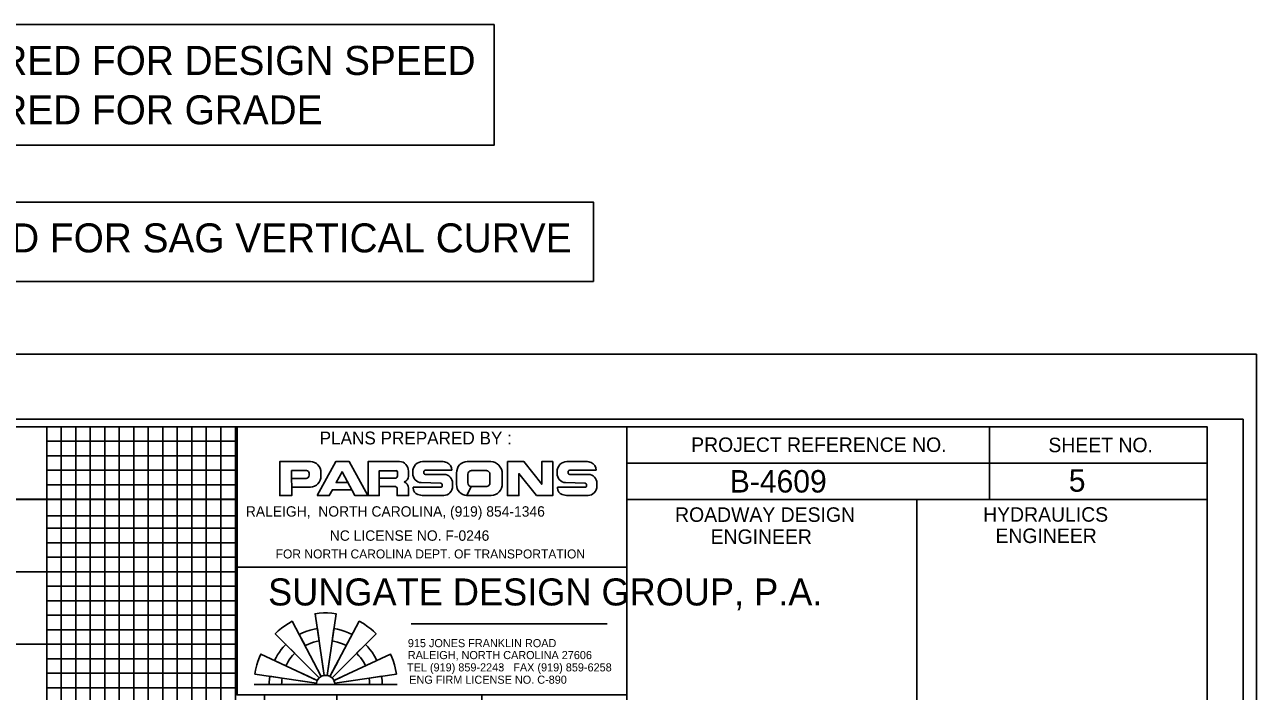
# Model space of a CAD drawing. Extents: x 1735444 to 1737729, y 696688 to 698970.
# Drawn here: x 1737304.4 to 1737729.1, y 698618.9 to 698848.7 of the extents above; entities that cross this region are included whole.
import ezdxf

# ---------------------------------------------------------------- set-up
doc = ezdxf.new("R2010")
doc.units = 0
for name, color, linetype in [('Default', 7, 'Continuous'), ('Old_Level_2', 7, 'Continuous'), ('Prop Grid Mask', 7, 'Continuous'), ('Prop VPI Label', 7, 'Continuous'), ('Sheet Cutting Line CELL', 7, 'Continuous'), ('Sheet Data Field CELL', 7, 'Continuous'), ('Sheet DOT Grid CELL', 7, 'Continuous'), ('Sheet Layout Profile Border', 7, 'Continuous'), ('Sheet Plot Border Inside CELL', 7, 'Continuous'), ('Sheet Plot Border Outside CELL', 7, 'Continuous'), ('Sheet Profile CELL', 7, 'Continuous'), ('Sheet Profile Grid Major CELL', 7, 'Continuous'), ('Sheet Profile Grid Middle CELL', 7, 'Continuous'), ('Sheet Profile Grid Minor CELL', 7, 'Continuous')]:
    doc.layers.add(name, color=color, linetype=linetype)

msp = doc.modelspace()

# ---------------------------------------------------------------- linework, layer by layer
at = {"layer": 'Default'}
for p, q in [((1737437.74, 698642.18), (1737505.24, 698642.18)), ((1737401.13, 698634.69), (1737401.13, 698634.69)), ((1737415.34, 698634.69), (1737415.34, 698634.69)), ((1737401.99, 698627.54), (1737405.96, 698623.53)), ((1737406.71, 698624.08), (1737404.06, 698629.07)), ((1737407.74, 698624.42), (1737406.91, 698630)), ((1737408.68, 698624.42), (1737409.5, 698630)), ((1737409.7, 698624.08), (1737412.36, 698629.07)), ((1737414.43, 698627.54), (1737410.45, 698623.53)), ((1737390.95, 698623.81), (1737390.95, 698623.81)), ((1737405.32, 698622.62), (1737400.21, 698625.02)), ((1737401.61, 698624.38), (1737401.61, 698624.38)), ((1737411.09, 698622.62), (1737416.2, 698625.02)), ((1737414.04, 698624.01), (1737411.09, 698622.62)), ((1737383.53, 698621.27), (1737432.88, 698621.27)), ((1737405.05, 698621.73), (1737399.47, 698622.57)), ((1737411.36, 698621.73), (1737416.95, 698622.57))]:
    msp.add_line(p, q, dxfattribs=at)
for points in [[(1737377.67, 698661.7), (1737512.07, 698661.7), (1737512.07, 698617.69), (1737377.67, 698617.69)], [(1737407.74, 698624.42), (1737404.59, 698645.68), (1737405.96, 698645.84), (1737407.49, 698645.93), (1737408.79, 698645.94), (1737410.36, 698645.85), (1737411.82, 698645.68), (1737408.68, 698624.42)], [(1737405.96, 698623.53), (1737390.83, 698638.79), (1737391.85, 698639.74), (1737392.99, 698640.69), (1737394.13, 698641.53), (1737395.38, 698642.35), (1737396.62, 698643.05), (1737406.71, 698624.08)], [(1737399.06, 698638.48), (1737399.98, 698638.94), (1737401.4, 698639.53), (1737402.92, 698640.03), (1737404.29, 698640.36), (1737405.35, 698640.55), (1737405.99, 698636.27), (1737404.98, 698636.09), (1737404.03, 698635.85), (1737403.05, 698635.53), (1737402.01, 698635.11), (1737401.09, 698634.66)], [(1737409.7, 698624.08), (1737419.79, 698643.05), (1737421.21, 698642.24), (1737422.78, 698641.18), (1737423.76, 698640.42), (1737424.69, 698639.63), (1737425.58, 698638.78), (1737410.45, 698623.53)], [(1737411.06, 698640.55), (1737412.24, 698640.34), (1737413.56, 698640.01), (1737414.89, 698639.58), (1737416.09, 698639.09), (1737417.36, 698638.48), (1737415.33, 698634.66), (1737414.61, 698635.02), (1737413.66, 698635.42), (1737412.29, 698635.88), (1737411.34, 698636.11), (1737410.43, 698636.27)], [(1737405.05, 698621.73), (1737383.8, 698624.87), (1737384.02, 698626.16), (1737384.48, 698628.04), (1737384.84, 698629.19), (1737385.39, 698630.65), (1737385.87, 698631.75), (1737405.32, 698622.62)], [(1737390.56, 698629.54), (1737391.11, 698630.63), (1737391.61, 698631.49), (1737392.26, 698632.47), (1737392.9, 698633.33), (1737393.61, 698634.18), (1737394.48, 698635.11), (1737397.53, 698632.04), (1737396.79, 698631.26), (1737396.22, 698630.57), (1737395.68, 698629.82), (1737395.15, 698628.98), (1737394.77, 698628.3), (1737394.47, 698627.7)], [(1737411.08, 698622.6), (1737430.54, 698631.76), (1737431, 698630.73), (1737431.47, 698629.5), (1737431.92, 698628.09), (1737432.22, 698626.98), (1737432.62, 698624.88), (1737411.36, 698621.73)], [(1737421.93, 698635.11), (1737422.72, 698634.28), (1737423.49, 698633.37), (1737424.2, 698632.42), (1737425.07, 698631.04), (1737425.85, 698629.56), (1737421.94, 698627.72), (1737421.44, 698628.69), (1737420.77, 698629.77), (1737420.22, 698630.53), (1737419.69, 698631.18), (1737418.89, 698632.04)], [(1737388.72, 698621.27), (1737388.73, 698622.11), (1737388.8, 698623.1), (1737388.92, 698624.11), (1737393.2, 698623.48), (1737393.11, 698622.76), (1737393.06, 698622.02), (1737393.04, 698621.27)], [(1737405.02, 698621.27), (1737405.03, 698621.51), (1737405.05, 698621.72), (1737405.17, 698622.23), (1737405.32, 698622.62), (1737405.48, 698622.91), (1737405.65, 698623.17), (1737405.82, 698623.38), (1737405.96, 698623.53), (1737406.33, 698623.84), (1737406.71, 698624.08), (1737406.98, 698624.21), (1737407.28, 698624.31), (1737407.55, 698624.38), (1737407.74, 698624.42), (1737408.22, 698624.45), (1737408.68, 698624.42), (1737408.95, 698624.37), (1737409.18, 698624.3), (1737409.43, 698624.21), (1737409.7, 698624.08), (1737410.1, 698623.83), (1737410.45, 698623.53), (1737410.63, 698623.34), (1737410.8, 698623.11), (1737410.94, 698622.9), (1737411.09, 698622.62), (1737411.27, 698622.16), (1737411.36, 698621.73), (1737411.39, 698621.49), (1737411.39, 698621.27)], [(1737427.49, 698624.12), (1737427.65, 698622.64), (1737427.7, 698621.3), (1737423.38, 698621.27), (1737423.34, 698622.37), (1737423.21, 698623.49)]]:
    msp.add_lwpolyline(points, close=True, dxfattribs=at)
for start, end in [(359.9999, 179.9999), (179.9999, 359.9999)]:
    msp.add_arc((1737468.51, 698627.29), 0.138, start, end, dxfattribs=at)
at = {"layer": 'Old_Level_2'}
for p, q in [((1737377.67, 698710.13), (1737512.07, 698710.13)), ((1737377.67, 698661.7), (1737377.67, 698710.13)), ((1737512.07, 698661.7), (1737512.07, 698710.13)), ((1737448.26, 698698.11), (1737441.61, 698698.11)), ((1737465.13, 698698.11), (1737457, 698698.11)), ((1737498.01, 698698.11), (1737491.36, 698698.11)), ((1737402.49, 698693.37), (1737402.49, 698694.06)), ((1737406.57, 698694.29), (1737406.57, 698693.14)), ((1737432.98, 698693.14), (1737432.98, 698694.44)), ((1737436.77, 698694.83), (1737436.77, 698693.06)), ((1737438.25, 698694.52), (1737438.25, 698694.05)), ((1737442.68, 698695.13), (1737451.68, 698695.13)), ((1737449.11, 698693.68), (1737442.68, 698693.68)), ((1737453.32, 698694.14), (1737453.32, 698690.23)), ((1737457.28, 698690.77), (1737457.28, 698693.75)), ((1737458.41, 698694.98), (1737463.72, 698694.98)), ((1737464.85, 698693.75), (1737464.85, 698690.77)), ((1737469.1, 698690.54), (1737469.1, 698693.83)), ((1737488.01, 698694.52), (1737488.01, 698694.05)), ((1737492.44, 698695.13), (1737501.44, 698695.13)), ((1737498.87, 698693.68), (1737492.44, 698693.68)), ((1737441.19, 698690.84), (1737447.75, 698690.69)), ((1737451.97, 698689.69), (1737451.97, 698690.62)), ((1737456.86, 698686.41), (1737458.41, 698689.55)), ((1737490.95, 698690.84), (1737497.51, 698690.69)), ((1737501.73, 698689.69), (1737501.72, 698690.62)), ((1737442.04, 698686.41), (1737448.9, 698686.41)), ((1737456.86, 698686.41), (1737465.28, 698686.41)), ((1737491.79, 698686.41), (1737498.66, 698686.41)), ((1737512.07, 698661.7), (1737377.67, 698661.7))]:
    msp.add_line(p, q, dxfattribs=at)
for points in [[(1737401.63, 698694.98), (1737396.47, 698694.98), (1737396.47, 698692.3), (1737396.54, 698689.31), (1737396.54, 698686.41), (1737392.38, 698686.41), (1737392.38, 698698.11), (1737402.99, 698698.11)], [(1737432.48, 698694.97), (1737426.69, 698694.97), (1737426.69, 698692.37), (1737426.69, 698689.54), (1737426.69, 698686.41), (1737422.83, 698686.41), (1737422.83, 698698.11), (1737433.69, 698698.11)], [(1737402.99, 698689.31), (1737396.54, 698689.31), (1737396.47, 698692.3), (1737401.49, 698692.3)], [(1737436.77, 698688.93), (1737436.77, 698686.41), (1737432.84, 698686.41), (1737432.84, 698689.09), (1737432.34, 698689.54), (1737426.69, 698689.54), (1737426.69, 698692.37), (1737432.26, 698692.37)], [(1737447.75, 698689.24), (1737438.39, 698689.24), (1737438.39, 698689.01)], [(1737463.72, 698689.55), (1737458.41, 698689.55), (1737456.86, 698686.41), (1737465.28, 698686.41)], [(1737497.51, 698689.24), (1737488.15, 698689.24), (1737488.15, 698689.01)]]:
    msp.add_lwpolyline(points, dxfattribs=at)
for points in [[(1737405.23, 698686.41), (1737411.67, 698698.11), (1737416.34, 698698.11), (1737422.71, 698686.41), (1737418.32, 698686.41), (1737413.86, 698694.6), (1737411.81, 698690.84), (1737415.91, 698690.84), (1737417.25, 698688.4), (1737410.53, 698688.4), (1737409.47, 698686.41)], [(1737470.89, 698698.11), (1737470.89, 698686.41), (1737474.85, 698686.41), (1737474.85, 698693.98), (1737480.93, 698686.41), (1737486.52, 698686.41), (1737486.52, 698698.11), (1737482.7, 698698.11), (1737482.7, 698690.31), (1737476.55, 698698.11)]]:
    msp.add_lwpolyline(points, close=True, dxfattribs=at)
for centre, major_axis, ratio, start_param, end_param in [((1737402.99, 698694.29), (0, 3.83), 0.93676, 4.712389, 6.283185), ((1737433.69, 698694.82), (0, 3.29), 0.934072, 4.712389, 6.283185), ((1737441.61, 698694.52), (0, 3.6), 0.934072, 0, 1.570796), ((1737448.25, 698693.14), (0, 4.97), 0.934072, 5.902203, 6.283185), ((1737448.97, 698695.05), (0, 2.91), 0.934072, 4.738699, 5.901866), ((1737457, 698694.13), (0, 3.98), 0.924824, 0, 1.570796), ((1737465.13, 698693.83), (0, 4.28), 0.924824, 4.712389, 6.283185), ((1737491.37, 698694.52), (0, 3.6), 0.934072, 0, 1.570796), ((1737498.01, 698693.14), (0, 4.97), 0.934072, 5.902203, 6.283185), ((1737498.73, 698695.05), (0, 2.91), 0.934072, 4.738699, 5.901866), ((1737401.49, 698693.37), (0, 1.07), 0.93676, 3.141593, 4.712389), ((1737401.63, 698694.06), (0, 0.918), 0.93676, 4.712389, 6.283185), ((1737402.99, 698693.14), (0, 3.83), 0.93676, 3.141593, 4.712389), ((1737432.26, 698693.14), (0, 0.765), 0.934072, 3.141593, 4.712389), ((1737432.48, 698694.44), (0, 0.536), 0.934072, 4.712389, 6.283185), ((1737434.91, 698693.06), (0, 1.99), 0.934072, 3.34512, 4.712389), ((1737434.62, 698688.93), (0, 2.3), 0.934072, 4.712389, 5.969561), ((1737441.25, 698694.05), (0, -3.21), 0.934072, 4.712389, 6.260753), ((1737442.68, 698694.4), (0, 0.727), 0.934072, 0, 3.141593), ((1737449.11, 698690.61), (0, 3.06), 0.934072, 4.712389, 6.283185), ((1737458.41, 698693.75), (0, -1.22), 0.924824, 3.141593, 4.712389), ((1737463.72, 698693.75), (0, 1.22), 0.924824, 4.712389, 6.283185), ((1737491.01, 698694.05), (0, -3.21), 0.934072, 4.712389, 6.260753), ((1737492.44, 698694.4), (0, 0.727), 0.934072, 0, 3.141593), ((1737498.87, 698690.61), (0, 3.06), 0.934072, 4.712389, 6.283185), ((1737440.61, 698689.01), (0, -2.37), 0.934072, 4.712389, 5.988639), ((1737447.75, 698689.96), (0, 0.727), 0.934072, 3.141593, 6.283185), ((1737448.9, 698689.7), (0, 3.29), 0.934072, 3.141593, 4.712389), ((1737456.86, 698690.23), (0, -3.83), 0.924824, 4.712389, 6.283185), ((1737458.41, 698690.77), (0, -1.22), 0.924824, 4.712389, 6.283185), ((1737463.72, 698690.77), (0, 1.22), 0.924824, 3.141593, 4.712389), ((1737465.28, 698690.54), (0, 4.13), 0.924824, 3.141593, 4.712389), ((1737490.37, 698689.01), (0, -2.37), 0.934072, 4.712389, 5.988639), ((1737497.51, 698689.96), (0, 0.727), 0.934072, 3.141593, 6.283185), ((1737498.65, 698689.7), (0, 3.29), 0.934072, 3.141593, 4.712389), ((1737442.04, 698694.06), (0, 7.65), 0.934072, 2.847261, 3.141593), ((1737491.79, 698694.06), (0, 7.65), 0.934072, 2.847261, 3.141593)]:
    msp.add_ellipse(centre, major_axis=major_axis, ratio=ratio, start_param=start_param, end_param=end_param, dxfattribs=at)
at = {"layer": 'Prop Grid Mask'}
for points in [[(1737104.37, 698848.7), (1737466.25, 698848.7), (1737466.25, 698807.13), (1737104.37, 698807.13)], [(1737089.89, 698787.53), (1737500.51, 698787.53), (1737500.51, 698760.21), (1737089.89, 698760.21)]]:
    msp.add_lwpolyline(points, close=True, dxfattribs=at)
at = {"layer": 'Sheet Cutting Line CELL'}
msp.add_line((1737729.07, 698735.13), (1736045.07, 698735.13), dxfattribs=at)
at = {"layer": 'Sheet DOT Grid CELL'}
for p, q in [((1737362.07, 698710.13), (1737362.07, 697685.13)), ((1737412.07, 698710.13), (1737412.07, 698710.09)), ((1737462.07, 698710.13), (1737462.07, 698710.09)), ((1736212.07, 698685.13), (1737377.62, 698685.13)), ((1736212.07, 698635.13), (1737377.67, 698635.13))]:
    msp.add_line(p, q, dxfattribs=at)
at = {"layer": 'Sheet Layout Profile Border'}
for points in [[(1737512.02, 698661.7), (1737512.02, 698710.13), (1736262.07, 698710.13), (1736262.07, 697685.13), (1737662.07, 697685.13), (1737662.07, 698572.58), (1737512.02, 698572.58), (1737512.02, 698617.69)], [(1737512.02, 698617.69), (1737512.02, 698661.7)]]:
    msp.add_lwpolyline(points, dxfattribs=at)
at = {"layer": 'Sheet Plot Border Inside CELL'}
msp.add_lwpolyline([(1737724.57, 698712.68), (1736058.07, 698712.68), (1736058.07, 697657.58), (1737724.57, 697657.58)], close=True, dxfattribs=at)
at = {"layer": 'Sheet Plot Border Outside CELL'}
msp.add_lwpolyline([(1737729.07, 698735.13), (1736045.07, 698735.13), (1736045.07, 697635.13), (1737729.07, 697635.13)], close=True, dxfattribs=at)
at = {"layer": 'Sheet Profile CELL'}
for p, q in [((1737637.07, 698710.08), (1737637.07, 698685.08)), ((1737512.02, 698697.58), (1737712.07, 698697.58)), ((1737612.07, 698685.08), (1737612.07, 698572.63))]:
    msp.add_line(p, q, dxfattribs=at)
for points in [[(1737712.07, 698710.13), (1736212.07, 698710.13), (1736212.07, 697660.13), (1737712.07, 697660.13)], [(1737512.02, 698710.13), (1737712.07, 698710.13), (1737712.07, 698685.08), (1737512.02, 698685.08)], [(1737612.07, 698685.08), (1737712.07, 698685.08), (1737712.07, 698572.58), (1737612.07, 698572.58)]]:
    msp.add_lwpolyline(points, close=True, dxfattribs=at)
for points in [[(1737512.02, 698617.69), (1737512.02, 698572.58), (1737612.07, 698572.58), (1737612.07, 698685.08), (1737512.02, 698685.08), (1737512.02, 698661.7)], [(1737512.02, 698661.7), (1737512.07, 698661.7), (1737512.07, 698617.69), (1737512.02, 698617.69)]]:
    msp.add_lwpolyline(points, dxfattribs=at)
at = {"layer": 'Sheet Profile Grid Major CELL'}
for points in [[(1736962.07, 697685.13), (1737012.07, 697685.13), (1737012.07, 698710.13), (1737062.07, 698710.13), (1737062.07, 697685.13), (1737112.07, 697685.13), (1737112.07, 698710.13), (1737162.07, 698710.13), (1737162.07, 697685.13), (1737212.07, 697685.13), (1737212.07, 698710.13), (1737262.07, 698710.13), (1737262.07, 697685.13), (1737312.07, 697685.13), (1737312.07, 698710.13), (1737362.07, 698710.13), (1737362.07, 697685.13), (1737412.07, 697685.13), (1737412.07, 698617.69)], [(1737412.07, 698710.09), (1737412.07, 698710.13), (1737462.07, 698710.13), (1737462.07, 698710.09)], [(1737462.07, 698617.69), (1737462.07, 697685.13), (1737512.07, 697685.13), (1737512.07, 698710.13), (1737538.37, 698710.13)], [(1737377.67, 698635.13), (1736212.17, 698635.13), (1736212.17, 698685.08), (1737377.62, 698685.08)]]:
    msp.add_lwpolyline(points, dxfattribs=at)
at = {"layer": 'Sheet Profile Grid Middle CELL'}
for points in [[(1737312.07, 698710.13), (1737312.07, 698710.13), (1737337.07, 698710.13), (1737337.07, 697685.13), (1737387.07, 697685.13), (1737387.07, 698617.69)], [(1737387.07, 698710.09), (1737387.07, 698710.13), (1737437.07, 698710.13), (1737437.07, 698710.09)], [(1737487.07, 698710.09), (1737487.07, 698710.13)], [(1736212.07, 698660.13), (1737377.67, 698660.13)]]:
    msp.add_lwpolyline(points, dxfattribs=at)
at = {"layer": 'Sheet Profile Grid Minor CELL'}
for points in [[(1737317.07, 697685.13), (1737317.07, 698710.13), (1737322.07, 698710.13), (1737322.07, 697685.13)], [(1737327.07, 697685.13), (1737327.07, 698710.13), (1737332.07, 698710.13), (1737332.07, 697685.13)], [(1737342.07, 697685.13), (1737342.07, 698710.13), (1737347.07, 698710.13), (1737347.07, 697685.13)], [(1737352.07, 697685.13), (1737352.07, 698710.13), (1737357.07, 698710.13), (1737357.07, 697685.13)], [(1737367.07, 697685.13), (1737367.07, 698710.13), (1737372.07, 698710.13), (1737372.07, 697685.13)], [(1737377.07, 697685.13), (1737377.07, 698710.13), (1737382.07, 698710.13), (1737382.07, 698710.09)], [(1737392.07, 698710.09), (1737392.07, 698710.13), (1737397.07, 698710.13), (1737397.07, 698710.09)], [(1737402.07, 698710.09), (1737402.07, 698710.13), (1737407.07, 698710.13), (1737407.07, 698710.09)], [(1737417.07, 698710.09), (1737417.07, 698710.13), (1737422.07, 698710.13), (1737422.07, 698710.09)], [(1737427.07, 698710.09), (1737427.07, 698710.13), (1737432.07, 698710.13), (1737432.07, 698710.09)], [(1737442.07, 698710.09), (1737442.07, 698710.13), (1737447.07, 698710.13), (1737447.07, 698710.09)], [(1737452.07, 698710.09), (1737452.07, 698710.13), (1737457.07, 698710.13), (1737457.07, 698710.09)], [(1737467.07, 698710.09), (1737467.07, 698710.13), (1737472.07, 698710.13), (1737472.07, 698710.09)], [(1737477.07, 698710.09), (1737477.07, 698710.13), (1737482.07, 698710.13), (1737482.07, 698710.09)], [(1737492.07, 698710.09), (1737492.07, 698710.13), (1737497.07, 698710.13), (1737497.07, 698710.09)], [(1737502.07, 698710.09), (1737502.07, 698710.13), (1737507.07, 698710.13), (1737507.07, 698710.09)], [(1737377.62, 698705.13), (1737312.07, 698705.13)], [(1737312.07, 698700.13), (1737377.62, 698700.13)], [(1737377.62, 698695.13), (1737312.07, 698695.13)], [(1737312.07, 698690.13), (1737377.62, 698690.13)], [(1737377.62, 698679.38), (1737312.07, 698679.38)], [(1737312.07, 698675.13), (1737377.62, 698675.13)], [(1737377.62, 698670.13), (1737312.07, 698670.13)], [(1737312.07, 698665.13), (1737377.62, 698665.13)], [(1737377.67, 698655.13), (1737312.07, 698655.13)], [(1737312.07, 698650.13), (1737377.67, 698650.13)], [(1737377.67, 698645.13), (1737312.07, 698645.13)], [(1737312.07, 698640.13), (1737377.67, 698640.13)], [(1737377.67, 698630.13), (1737312.07, 698630.13)], [(1737312.07, 698625.13), (1737377.67, 698625.13)], [(1737377.67, 698620.13), (1737312.07, 698620.13)]]:
    msp.add_lwpolyline(points, dxfattribs=at)

# ---------------------------------------------------------------- texts
at = {"layer": 'Default'}
for s, height, p in [('SUNGATE DESIGN GROUP, P.A.', 9.3194, (1737388.36, 698648.51)), ('915 JONES FRANKLIN ROAD', 2.8007, (1737436.54, 698634.14)), ('RALEIGH, NORTH CAROLINA 27606', 2.8007, (1737436.54, 698630.02)), ('TEL (919) 859-2243   FAX (919) 859-6258', 2.8007, (1737436.25, 698625.78)), ('ENG FIRM LICENSE NO. C-890', 2.8007, (1737437.03, 698621.53))]:
    msp.add_text(s, height=height, rotation=359.9999, dxfattribs=at).set_placement(p)
at = {"layer": 'Old_Level_2'}
for s, height, rotation, p in [('PLANS PREPARED BY : ', 4.4145, 359.999, (1737406.14, 698704.02)), ('RALEIGH,  NORTH CAROLINA, (919) 854-1346', 3.5754, 360, (1737380.69, 698679.13)), ('NC LICENSE NO. F-0246', 3.5754, 360, (1737409.63, 698670.81)), ('FOR NORTH CAROLINA DEPT. OF TRANSPORTATION', 3.1013, 359.9999, (1737390.97, 698664.72))]:
    msp.add_text(s, height=height, rotation=rotation, dxfattribs=at).set_placement(p)
at = {"layer": 'Prop VPI Label'}
for s, p in [('* DESIGN EXCEPTION REQUIRED FOR DESIGN SPEED', (1737108.45, 698831.36)), ('* DESIGN EXCEPTION REQUIRED FOR GRADE', (1737108.45, 698814.33)), ('* DESIGN EXCEPTION REQUIRED FOR SAG VERTICAL CURVE', (1737093.97, 698770.2))]:
    msp.add_text(s, height=10, dxfattribs=at).set_placement(p)
at = {"layer": 'Sheet Data Field CELL'}
for s, p in [('5  ', (1737664.4, 698687.73)), ('B-4609   ', (1737547.53, 698687.43))]:
    msp.add_text(s, height=7.75, dxfattribs=at).set_placement(p)
at = {"layer": 'Sheet Profile CELL'}
for s, height, p in [('PROJECT REFERENCE NO.', 5.0001, (1737534.22, 698701.43)), ('SHEET NO.', 5, (1737657.37, 698701.33)), ('ROADWAY DESIGN', 5.0001, (1737528.67, 698677.33)), ('HYDRAULICS', 5, (1737634.87, 698677.38)), ('ENGINEER', 5, (1737540.92, 698669.73)), ('ENGINEER', 5, (1737639.12, 698670.03))]:
    msp.add_text(s, height=height, dxfattribs=at).set_placement(p)

doc.saveas('drawing.dxf')
